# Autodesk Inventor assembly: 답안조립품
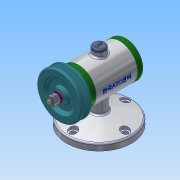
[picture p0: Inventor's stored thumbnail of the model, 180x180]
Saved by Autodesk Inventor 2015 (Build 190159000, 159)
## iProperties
Created: 2018-12
Part Number: 답안조립품
Document SubType Name: Assembly
Designer: 405-10
Author: 405-10
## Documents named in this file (15)
- C:\Users\405-10\Desktop\481207V1058\답안조립품.iam
- C:\Users\405-10\Desktop\481207V1058\본체.ipt
- C:\Users\405-10\Desktop\481207V1058\앞커버.ipt
- C:\Users\405-10\Desktop\481207V1058\뒤커버.ipt
- C:\Users\405-10\Desktop\481207V1058\축.ipt
- C:\Users\405-10\Desktop\481207V1058\베어링 15 x 32 x 9.ipt
- C:\Users\405-10\Desktop\481207V1058\오일 실 15 25 7.ipt
- C:\Users\405-10\Desktop\481207V1058\키 3 x 3 x 12.ipt
- C:\Users\405-10\Desktop\481207V1058\V벨트풀리.ipt
- C:\Users\405-10\Desktop\481207V1058\와셔 8x17.ipt
- C:\Users\405-10\Desktop\481207V1058\스프링와셔 8.ipt
- C:\Users\405-10\Desktop\481207V1058\너트 M8.ipt
- 너트 M8.ipt
- C:\Users\405-10\Desktop\481207V1058\볼트 M4 x 12.ipt
- C:\Users\405-10\Desktop\481207V1058\고무캡.ipt
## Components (2 placed, 2 different names)
1. V벨트풀리:1
2. 고무캡:1
